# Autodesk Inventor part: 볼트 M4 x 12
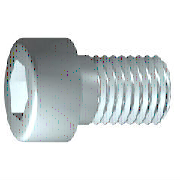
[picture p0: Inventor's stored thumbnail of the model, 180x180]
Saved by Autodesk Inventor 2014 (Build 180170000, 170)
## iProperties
IsCustomPart: 0
Created: 2012-02
Part Number: 볼트 M4 x 12
Material: 스테인리스강
Description: 6각 소켓 머리 캡 나사
Document SubType Name: Modeling
Standard: ISO 4762
Designer: mduedu
Standard Revision: Fourth edition 2004-03-01
Standards Organization: ISO
Language: ko-KR
Size Designation: M4 x 12
Categories: <MemberInstance><Categories><Category DisplayName="조임쇠" InternalName="e4da775c-781d-43d5-af7c-5136215cf5a6" Mnemonic="FSTN"><Category DisplayName="볼트" InternalN
Density: 8.08 g/cm^3
Appearance: Default
Author: mduedu
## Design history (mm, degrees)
sketch "스케치1"
  geometry: L1 (-1, 0)-(12, 0); L2 (12, 0)-(12, 2); L3 (12, 2)-(1.75, 2); L4 (1.75, 2)-(1.32, 2); L5 (1.32, 2)-(0, 2); L6 (0, 2)-(0, 3.5); L7 (0, 3.5)-(-4, 3.5); L8 (-4, 3.5)-(-4, 1.732); L9 (-4, 1.732)-(-2, 1.732); L10 (-2, 1.732)-(-1, 0); L11 (-7.2, 0)-(15.2, 0) reference; L12 (0, -0.7)-(0, 4.2) reference; L13 (1.75, 2)-(0, 2)
  constraints: 22 end point, 6 parallel, 2 collinear, 2 perpendicular, 1 horizontal, 1 point on line
  dimensions: "d1" = 10.25 distance from line of L3.end L2 (= GEL); "d2" = 0.42952 distance of L4.end L3.end (computed from GAL); "d3" = 4 distance between parallel lines of L8 L6 (= KOH); "d4" = 2 distance of L8.end L9.end (= INTI); "d5" = 60 deg angle of L10 L1; "d6" = 4 diameter of L3 L1 (= GD); "d7" = 4 diameter of L5 L1 (= BDM); "d8" = 3.4641 diameter of L9 L1 (= 1.1547 x SW); "d9" = 7 diameter of L7 L1 (= KOD); "d26" = 12 distance between parallel lines of L12 L2 (= NLG)
revolve "본체" sketch "스케치1" stored, may be unused: angle "d10" = 90 deg
sketch "스케치2"
  geometry: L1 (0, -4.9)-(0, 4.9) reference; L2 (-4.9, 0)-(4.9, 0) reference; L3 (1.732, 0)-(0.866, -1.5); L4 (0.866, -1.5)-(-0.866, -1.5); L5 (-0.866, -1.5)-(-1.732, 0); L6 (-1.732, 0)-(-0.866, 1.5); L7 (-0.866, 1.5)-(0.866, 1.5); L8 (0.866, 1.5)-(1.732, 0); 2 further points
  constraints: 12 end point, 1 coincident, 1 horizontal alignment, 1 point on line, 12 other
extrude "슬롯" join sketch "스케치2" stored distance "d11" = 10; taper "d12" = 0 deg
workplane "Work Plane1"
fillet "Fillet2" dims "d30" = 0.1 (= R)
body "Solid1"
fillet "모깎기1" dims "d17" = 0.4 (= RR)
feature "스레드" dims "d13" = 10.25 (= GEL), "d14" = 0
chamfer "모따기1" distance "d15" = 0.42941 (= -0.5 x SPD + 0.5 x GD); stored, may be unused: second distance "d16" = 0.42941 (= GUL), angle "d27" = 45 deg
other parameters: "GD" = 4 [user parameter; used in 2 equation terms], "NLG" = 12 [user parameter; used in 1 equation term], "GEL" = 10.25 [user parameter; used in 2 equation terms], "KOD" = 7 [user parameter; used in 1 equation term], "KOH" = 4 [user parameter; used in 1 equation term], "INTI" = 2 [user parameter; used in 1 equation term], "GAL" = 0.42941 (= 0.61345 x PTC) [user parameter; used in 1 equation term], "GUL" = 0.42941 (= 0.61345 x PTC) [user parameter; used in 1 equation term], "BDM" = 4 (= NND) [user parameter; used in 1 equation term], "SW" = 3 [user parameter; used in 2 equation terms], "RR" = 0.4 [user parameter; used in 1 equation term], "SPD" = 3.14117 (= NND - 1.2269 x PTC) [user parameter; used in 1 equation term], "d19" = 0, "d28" = 0, "d29" = 0, "R" = 0.1 [user parameter; used in 1 equation term], "TOA" = 30 deg [user parameter], "GD1" = 3.14117 (= THREADDIA - 1.2269 x PTC) [user parameter], "THREADDIA" = 4 [user parameter; used in 1 equation term], "FAWI" = 45 deg [user parameter], "TPU" = 14.28571 (computed from PTC) [user parameter], "PTC" = 0.7 [user parameter; used in 5 equation terms], "NND" = 4 [user parameter; used in 2 equation terms], "E0" = 3.465 (= 1.155 x SW) [user parameter]
